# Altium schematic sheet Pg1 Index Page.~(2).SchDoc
size 431 x 279 mm; Date: Not shown in title block; ApprovedBy: Not shown in title block; CheckedBy: Not shown in title block; Author: Not shown in title block; CompanyName: Not shown in title block; Engineer: Not shown in title block; Organization: Not shown in title block; Address1: Not shown in title block; Address2: Not shown in title block; Address3: Not shown in title block; Address4: Not shown in title block; DocumentNumber: 1; Revision: Use project parameter SCH_Rev; SheetNumber: 1; SheetTotal: 7; PageSetup: Record=PageOptions|CenterHorizontal=True|CenterVertical=True|PrintScale=1.00|XCorrection=1.00|YCorrection=1.00|PrintKind=0|BorderSize=5000000|LeftOffset=0|BottomOffset=0|Orientation=2|PaperLength=1000|PaperWidth=1000|Scale=100|PaperSource=15|PrintQuality=600|MediaType=1|DitherType=10|PaperKind=Letter|PrintScaleMode=1
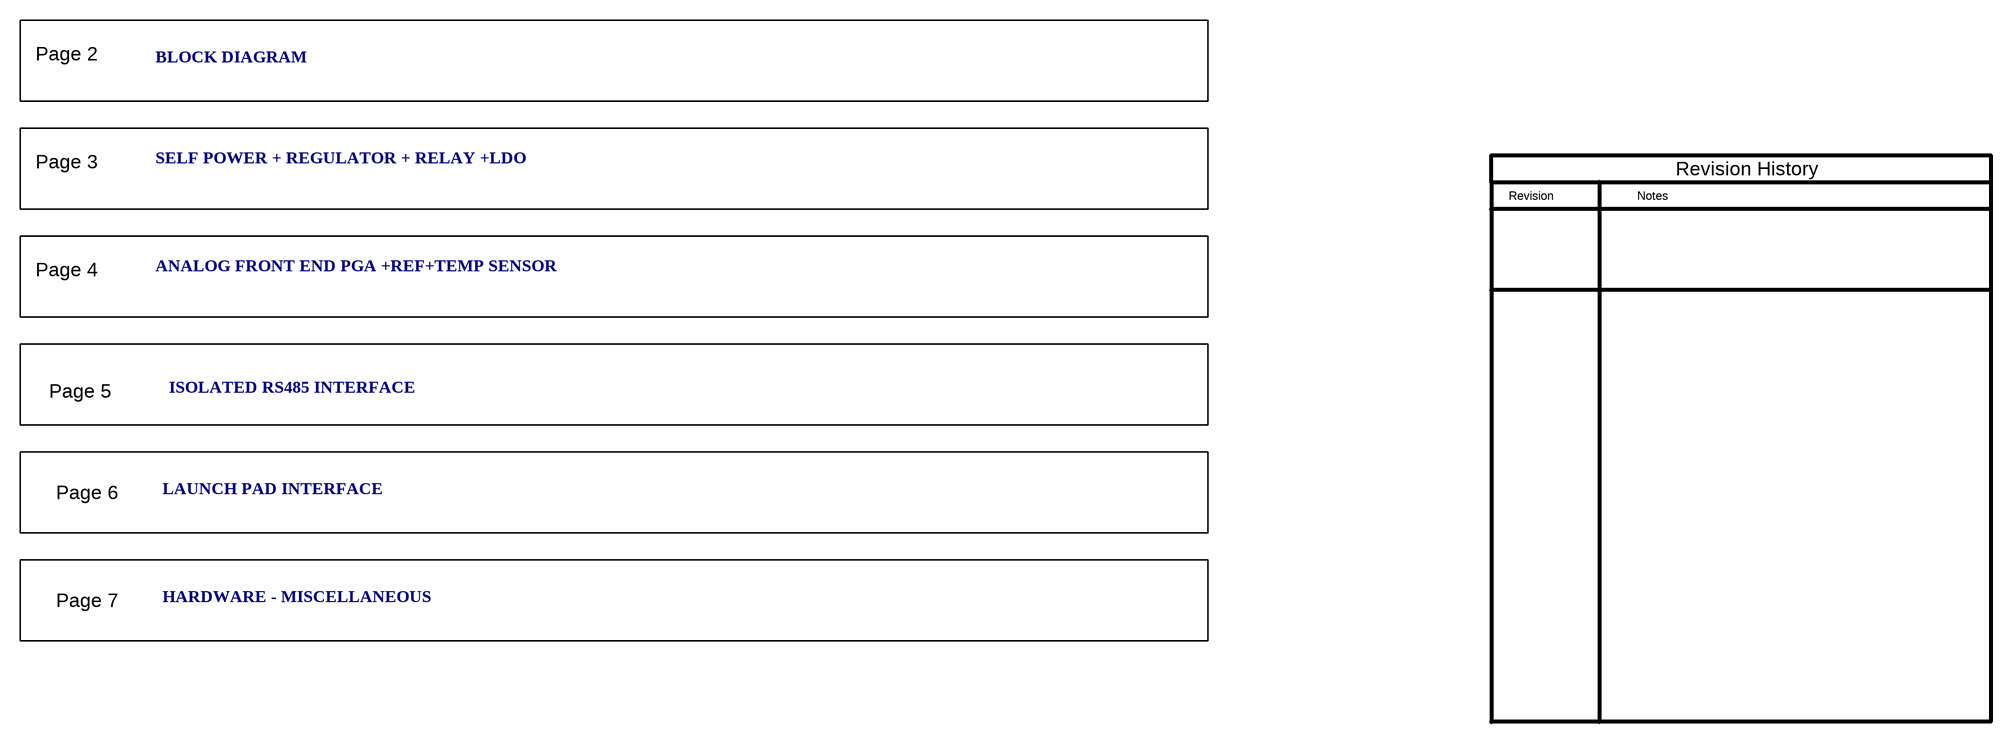
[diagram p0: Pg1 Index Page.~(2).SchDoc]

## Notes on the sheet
- Page 2
- BLOCK DIAGRAM
- Page 3
- SELF POWER + REGULATOR + RELAY +LDO
- Revision
- Notes
- Revision History
- Page 4
- ANALOG FRONT END PGA +REF+TEMP SENSOR
- Page 5
- ISOLATED RS485 INTERFACE
- Page 6
- LAUNCH PAD INTERFACE
- Page 7
- HARDWARE - MISCELLANEOUS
